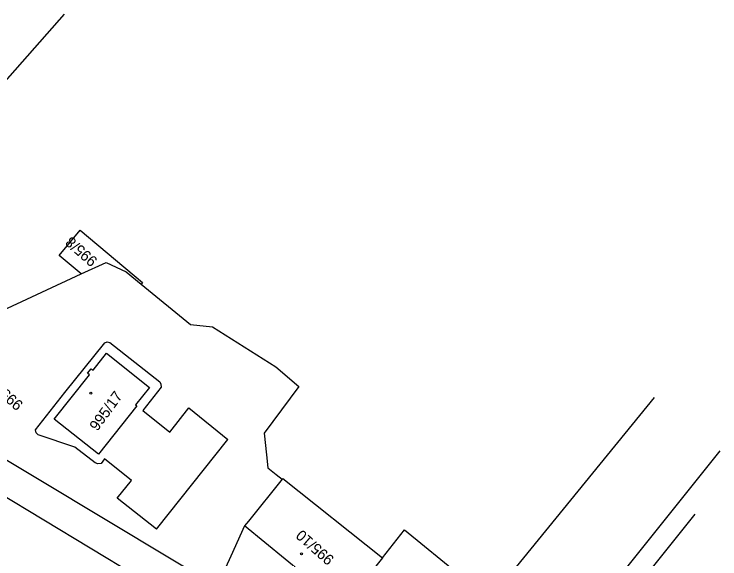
# Model space of a CAD drawing. Extents: x -496688 to -495455, y -1089309 to -1088026.
# Drawn here: x -495900.1 to -495768.9, y -1088339.8 to -1088238.6 of the extents above; entities that cross this region are included whole.
import ezdxf

# ---------------------------------------------------------------- set-up
doc = ezdxf.new("R2010")
doc.units = 0
for name, color, linetype in [('Vrstva 23', 7, 'Continuous'), ('Vrstva 52', 7, 'Continuous'), ('Vrstva 55', 7, 'Continuous'), ('Vrstva 57', 7, 'Continuous'), ('Vrstva 59', 7, 'Continuous')]:
    doc.layers.add(name, color=color, linetype=linetype)

msp = doc.modelspace()

# ---------------------------------------------------------------- linework, layer by layer
at = {"layer": 'Vrstva 23'}
for p, q in [((-495885.44, -1088304.75), (-495882.95, -1088301.61)), ((-495882.95, -1088301.61), (-495874.94, -1088307.95)), ((-495886.48, -1088305.33), (-495885.79, -1088304.47)), ((-495885.79, -1088304.47), (-495885.44, -1088304.75)), ((-495892.66, -1088313.83), (-495886.12, -1088305.61)), ((-495886.12, -1088305.61), (-495886.48, -1088305.33)), ((-495874.94, -1088307.95), (-495877.55, -1088311.19)), ((-495877.55, -1088311.19), (-495877.3, -1088311.4)), ((-495884.43, -1088320.36), (-495892.66, -1088313.83)), ((-495850.33, -1088325.03), (-495856.58, -1088332.83)), ((-495850.21, -1088324.89), (-495831.68, -1088339.62)), ((-495845.47, -1088343.35), (-495857.29, -1088333.7)), ((-495831.68, -1088339.62), (-495838.76, -1088348.52))]:
    msp.add_line(p, q, dxfattribs=at)
at = {"layer": 'Vrstva 52'}
msp.add_line((-495877.3, -1088311.4), (-495884.43, -1088320.36), dxfattribs=at)
at = {"layer": 'Vrstva 55'}
for p, q in [((-495890.83, -1088238.57), (-495904.99, -1088254.61)), ((-495891.76, -1088283.43), (-495887.83, -1088278.74)), ((-495887.83, -1088278.74), (-495876.26, -1088288.43)), ((-495887.65, -1088286.86), (-495891.76, -1088283.43)), ((-495887.65, -1088286.86), (-495883.04, -1088284.72)), ((-495883.04, -1088284.72), (-495879.3, -1088286.49)), ((-495927.53, -1088305.35), (-495887.65, -1088286.86)), ((-495879.3, -1088286.49), (-495876.53, -1088288.75)), ((-495876.26, -1088288.43), (-495876.53, -1088288.75)), ((-495876.53, -1088288.75), (-495867.32, -1088296.25)), ((-495867.32, -1088296.25), (-495863.28, -1088296.69)), ((-495863.28, -1088296.69), (-495851.51, -1088304.14)), ((-495890.69, -1088308.89), (-495883.29, -1088299.65)), ((-495883.29, -1088299.65), (-495882.81, -1088299.49)), ((-495882.81, -1088299.49), (-495882.37, -1088299.59)), ((-495882.37, -1088299.59), (-495873.04, -1088306.92)), ((-495851.51, -1088304.14), (-495847.2, -1088307.8)), ((-495873.04, -1088306.92), (-495872.83, -1088307.36)), ((-495872.81, -1088307.89), (-495876.23, -1088312.24)), ((-495872.83, -1088307.36), (-495872.81, -1088307.89)), ((-495847.2, -1088307.8), (-495853.66, -1088316.45)), ((-495896.16, -1088315.86), (-495890.69, -1088308.89)), ((-495811.71, -1088347.34), (-495781.1, -1088309.8)), ((-495876.23, -1088312.24), (-495871.19, -1088316.25)), ((-495871.19, -1088316.25), (-495867.63, -1088311.77)), ((-495867.63, -1088311.77), (-495860.39, -1088317.62)), ((-495923.01, -1088315.43), (-495872.67, -1088345.79)), ((-495896.01, -1088316.37), (-495896.16, -1088315.86)), ((-495895.67, -1088316.74), (-495896.01, -1088316.37)), ((-495888.82, -1088319.06), (-495895.67, -1088316.74)), ((-495873.65, -1088334.29), (-495860.39, -1088317.62)), ((-495853.66, -1088316.45), (-495853.23, -1088320.45)), ((-495903.67, -1088320.15), (-495895.49, -1088325.07)), ((-495885.04, -1088321.98), (-495888.82, -1088319.06)), ((-495768.94, -1088319.71), (-495810.36, -1088371.39)), ((-495883.31, -1088321.25), (-495883.98, -1088322.1)), ((-495878.31, -1088325.22), (-495883.31, -1088321.25)), ((-495853.23, -1088320.45), (-495852.97, -1088322.88)), ((-495884.55, -1088322.15), (-495885.04, -1088321.98)), ((-495883.98, -1088322.1), (-495884.55, -1088322.15)), ((-495852.97, -1088322.88), (-495851.44, -1088324.14)), ((-495851.44, -1088324.14), (-495850.33, -1088325.03)), ((-495895.49, -1088325.07), (-495870.94, -1088339.78)), ((-495880.96, -1088328.56), (-495878.31, -1088325.22)), ((-495850.33, -1088325.03), (-495850.21, -1088324.89)), ((-495873.65, -1088334.29), (-495880.96, -1088328.56)), ((-495773.57, -1088331.51), (-495804.86, -1088370.43)), ((-495856.58, -1088332.83), (-495857.29, -1088333.7)), ((-495857.29, -1088333.7), (-495859.86, -1088339.34)), ((-495831.68, -1088339.62), (-495827.55, -1088334.41)), ((-495827.55, -1088334.41), (-495811.71, -1088347.34)), ((-495870.94, -1088339.78), (-495865.85, -1088342.83)), ((-495859.86, -1088339.34), (-495861.62, -1088343.21))]:
    msp.add_line(p, q, dxfattribs=at)
at = {"layer": 'Vrstva 59'}
for centre in [(-495885.873, -1088309.035), (-495846.697, -1088338.887)]:
    msp.add_circle(centre, 0.175, dxfattribs=at)

# ---------------------------------------------------------------- texts
at = {"layer": 'Vrstva 57'}
for s, rotation, p in [('995/8', 138.55661, (-495884.486, -1088284.189)), ('995/18', 138.55661, (-495898.302, -1088310.928)), ('995/17', 53.89837, (-495884.667, -1088316.204)), ('995/10', 138.55661, (-495840.491, -1088339.668))]:
    msp.add_text(s, height=2, rotation=rotation, dxfattribs=at).set_placement(p)

doc.saveas('drawing.dxf')
